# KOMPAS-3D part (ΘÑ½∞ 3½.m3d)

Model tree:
1. Эскиз:1
2. Операция выдавливания:1
     Расстояние 1 = 2
3. Эскиз:2
4. Операция выдавливания:2
     Расстояние 1 = 5
5. Эскиз:3
6. Операция выдавливания:3
     Расстояние 1 = 2
7. Эскиз:4
8. Операция выдавливания:4
     Расстояние 1 = 78
9. Эскиз:5
10. Операция выдавливания:5
     Расстояние 1 = 2
11. Эскиз:6
12. Операция выдавливания:6
     Расстояние 1 = 4.5
13. Эскиз:7
14. Операция выдавливания:7
     Расстояние 1 = 2
15. Скругление:1
     Радиус = 1
16. Скругление:2
     Радиус = 1
17. Эскиз:8
18. Вырезать элемент выдавливания:1
     Расстояние 1 = 10; Угол 1 = 35
19. Эскиз:9
20. Вырезать элемент выдавливания:2
     Расстояние 1 = 10; Угол 1 = 35
21. Эскиз:10
22. Вырезать элемент выдавливания:3
     Расстояние 2 = 22; Расстояние 1 = 22; Угол 1 = 35
23. Эскиз:11
24. Вырезать элемент выдавливания:4
     Расстояние 2 = 2; Расстояние 1 = 2
25. Эскиз:12
26. Вырезать элемент выдавливания:5
     Расстояние 2 = 2; Расстояние 1 = 2; Угол 1 = 35
27. Эскиз:13
28. Вырезать элемент выдавливания:6
     Расстояние 2 = 2; Расстояние 1 = 122
29. Эскиз:14
30. Вырезать элемент выдавливания:7
     Расстояние 2 = 100; Расстояние 1 = 60
